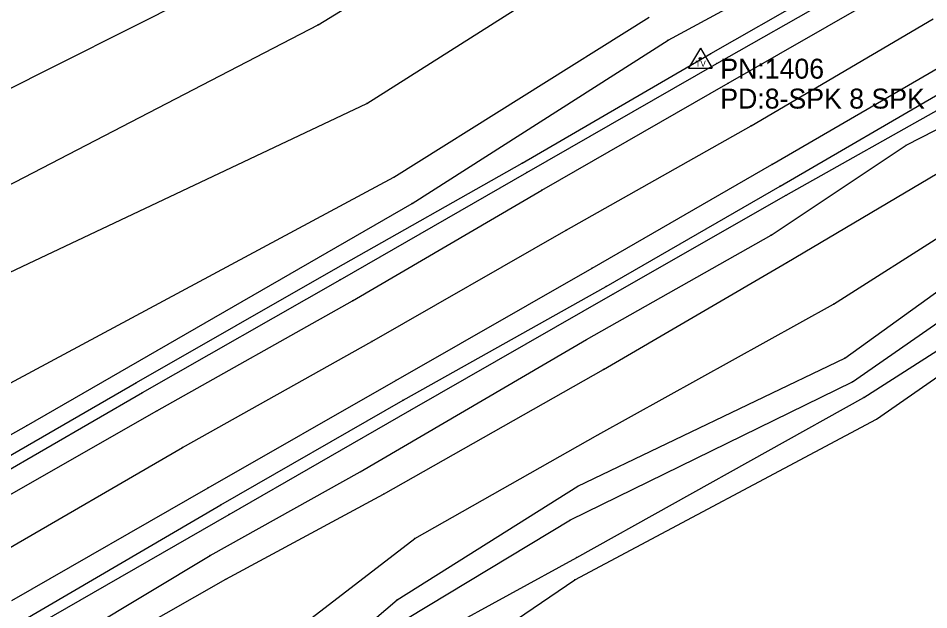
# Model space of a CAD drawing. Extents: x 1419505 to 1434054, y 1956910 to 1968644.
# Drawn here: x 1420365.7 to 1420594.1, y 1957394.5 to 1957542.8 of the extents above; entities that cross this region are included whole.
import ezdxf

# ---------------------------------------------------------------- set-up
doc = ezdxf.new("R2010")
doc.units = 0
for name, color, linetype in [('S_BREAKLINE', 7, 'Continuous'), ('S_DITCHLINE', 7, 'Continuous'), ('S_EDGE_PAVEMENT', 7, 'Continuous'), ('S_GRD_PT_SYM', 7, 'Continuous'), ('S_PAVEMENT_CROWN', 7, 'Continuous'), ('S_RDW_PT_SYM', 7, 'Continuous'), ('S_SECONDARY_CTL', 7, 'Continuous'), ('S_SECONDARY_CTL_ANNOT', 7, 'Continuous'), ('S_SHOULDER', 7, 'Continuous')]:
    doc.layers.add(name, color=color, linetype=linetype)

msp = doc.modelspace()

# ---------------------------------------------------------------- linework, layer by layer
at = {"layer": 'S_BREAKLINE'}
for p, q in [((1420440.9487, 1957541.147), (1420500.0875, 1957577.4944)), ((1420528.7223, 1957537.3228), (1420582.9688, 1957566.8997)), ((1420336.8469, 1957511.6521), (1420430.621, 1957558.8422)), ((1420453.1484, 1957521.3868), (1420512.2663, 1957558.9042)), ((1420539.463, 1957533.9656), (1420585.467, 1957560.2123)), ((1420459.9679, 1957502.9656), (1420523.993, 1957543.0132)), ((1420335.9639, 1957486.7575), (1420440.9487, 1957541.147)), ((1420464.5292, 1957496.3902), (1420528.7223, 1957537.3228)), ((1420588.4272, 1957510.9861), (1420638.2634, 1957536.4857)), ((1420492.082, 1957506.4418), (1420539.463, 1957533.9656)), ((1420558.3322, 1957498.4813), (1420604.7072, 1957524.557)), ((1420342.7853, 1957469.2664), (1420453.1484, 1957521.3868)), ((1420554.566, 1957488.4236), (1420588.4272, 1957510.9861)), ((1420445.4049, 1957480.0481), (1420492.082, 1957506.4418)), ((1420558.5302, 1957481.5912), (1420598.4178, 1957505.2107)), ((1420361.3455, 1957450.0972), (1420459.9679, 1957502.9656)), ((1420367.7909, 1957440.5896), (1420464.5292, 1957496.3902)), ((1420514.8634, 1957473.6247), (1420558.3322, 1957498.4813)), ((1420570.161, 1957471.0985), (1420610.1676, 1957496.5682)), ((1420573.0112, 1957457.6237), (1420619.5492, 1957491.0488)), ((1420508.274, 1957462.254), (1420554.566, 1957488.4236)), ((1420512.5023, 1957454.7755), (1420558.5302, 1957481.5912)), ((1420581.0057, 1957442.2667), (1420636.4663, 1957481.1622)), ((1420395.4067, 1957451.5023), (1420445.4049, 1957480.0481)), ((1420463.9601, 1957444.4428), (1420514.8634, 1957473.6247)), ((1420511.1042, 1957438.3474), (1420570.161, 1957471.0985)), ((1420451.5093, 1957429.0728), (1420508.274, 1957462.254)), ((1420506.0919, 1957425.5396), (1420573.0112, 1957457.6237)), ((1420457.3207, 1957423.4785), (1420512.5023, 1957454.7755)), ((1420349.1857, 1957424.8305), (1420395.4067, 1957451.5023)), ((1420418.6102, 1957418.4271), (1420463.9601, 1957444.4428)), ((1420505.3308, 1957402.0491), (1420581.0057, 1957442.2667)), ((1420246.7721, 1957373.2022), (1420367.7909, 1957440.5896)), ((1420465.1742, 1957412.4227), (1420511.1042, 1957438.3474)), ((1420413.8669, 1957408.1525), (1420451.5093, 1957429.0728)), ((1420417.8422, 1957402.2331), (1420457.3207, 1957423.4785)), ((1420460.7409, 1957397.0417), (1420506.0919, 1957425.5396)), ((1420367.2719, 1957388.9172), (1420418.6102, 1957418.4271)), ((1420427.1558, 1957383.1318), (1420465.1742, 1957412.4227)), ((1420378.5366, 1957386.9371), (1420413.8669, 1957408.1525)), ((1420382.7719, 1957382.3268), (1420417.8422, 1957402.2331)), ((1420451.2933, 1957365.4267), (1420505.3308, 1957402.0491)), ((1420433.9602, 1957374.1033), (1420460.7409, 1957397.0417))]:
    msp.add_line(p, q, dxfattribs=at)
at = {"layer": 'S_DITCHLINE'}
for p, q in [((1420574.9243, 1957451.6853), (1420624.6025, 1957486.1255)), ((1420577.8055, 1957447.707), (1420634.0221, 1957483.6623)), ((1420504.2557, 1957417.073), (1420574.9243, 1957451.6853)), ((1420505.7998, 1957407.6324), (1420577.8055, 1957447.707)), ((1420454.7835, 1957387.2761), (1420504.2557, 1957417.073)), ((1420449.0972, 1957376.6484), (1420505.7998, 1957407.6324))]:
    msp.add_line(p, q, dxfattribs=at)
at = {"layer": 'S_EDGE_PAVEMENT'}
for p, q in [((1420543.8053, 1957526.5091), (1420589.4702, 1957552.7048)), ((1420554.712, 1957506.0958), (1420600.3439, 1957532.6105)), ((1420497.0183, 1957499.6924), (1420543.8053, 1957526.5091)), ((1420509.6311, 1957480.1821), (1420554.712, 1957506.0958)), ((1420449.5322, 1957471.9216), (1420497.0183, 1957499.6924)), ((1420460.4209, 1957451.9523), (1420509.6311, 1957480.1821)), ((1420400.517, 1957444.3878), (1420449.5322, 1957471.9216)), ((1420413.3409, 1957425.0856), (1420460.4209, 1957451.9523)), ((1420352.896, 1957417.206), (1420400.517, 1957444.3878)), ((1420364.1637, 1957396.8567), (1420413.3409, 1957425.0856))]:
    msp.add_line(p, q, dxfattribs=at)
at = {"layer": 'S_GRD_PT_SYM'}
for points in [[(1420440.9487, 1957541.147), (1420440.9487, 1957541.197), (1420440.9487, 1957541.147), (1420440.8987, 1957541.147), (1420440.9487, 1957541.147), (1420440.9487, 1957541.097), (1420440.9487, 1957541.147), (1420440.9987, 1957541.147)], [(1420528.7223, 1957537.3228), (1420528.7223, 1957537.3728), (1420528.7223, 1957537.3228), (1420528.6723, 1957537.3228), (1420528.7223, 1957537.3228), (1420528.7223, 1957537.2728), (1420528.7223, 1957537.3228), (1420528.7723, 1957537.3228)], [(1420539.463, 1957533.9656), (1420539.463, 1957534.0156), (1420539.463, 1957533.9656), (1420539.413, 1957533.9656), (1420539.463, 1957533.9656), (1420539.463, 1957533.9156), (1420539.463, 1957533.9656), (1420539.513, 1957533.9656)], [(1420453.1484, 1957521.3868), (1420453.1484, 1957521.4368), (1420453.1484, 1957521.3868), (1420453.0984, 1957521.3868), (1420453.1484, 1957521.3868), (1420453.1484, 1957521.3368), (1420453.1484, 1957521.3868), (1420453.1984, 1957521.3868)], [(1420588.4272, 1957510.9861), (1420588.4272, 1957511.0361), (1420588.4272, 1957510.9861), (1420588.3772, 1957510.9861), (1420588.4272, 1957510.9861), (1420588.4272, 1957510.9361), (1420588.4272, 1957510.9861), (1420588.4772, 1957510.9861)], [(1420492.082, 1957506.4418), (1420492.082, 1957506.4918), (1420492.082, 1957506.4418), (1420492.032, 1957506.4418), (1420492.082, 1957506.4418), (1420492.082, 1957506.3918), (1420492.082, 1957506.4418), (1420492.132, 1957506.4418)], [(1420459.9679, 1957502.9656), (1420459.9679, 1957503.0156), (1420459.9679, 1957502.9656), (1420459.9179, 1957502.9656), (1420459.9679, 1957502.9656), (1420459.9679, 1957502.9156), (1420459.9679, 1957502.9656), (1420460.0179, 1957502.9656)], [(1420464.5292, 1957496.3902), (1420464.5292, 1957496.4402), (1420464.5292, 1957496.3902), (1420464.4792, 1957496.3902), (1420464.5292, 1957496.3902), (1420464.5292, 1957496.3402), (1420464.5292, 1957496.3902), (1420464.5792, 1957496.3902)], [(1420558.3322, 1957498.4813), (1420558.3322, 1957498.5313), (1420558.3322, 1957498.4813), (1420558.2822, 1957498.4813), (1420558.3322, 1957498.4813), (1420558.3322, 1957498.4313), (1420558.3322, 1957498.4813), (1420558.3822, 1957498.4813)], [(1420554.566, 1957488.4236), (1420554.566, 1957488.4736), (1420554.566, 1957488.4236), (1420554.516, 1957488.4236), (1420554.566, 1957488.4236), (1420554.566, 1957488.3736), (1420554.566, 1957488.4236), (1420554.616, 1957488.4236)], [(1420558.5302, 1957481.5912), (1420558.5302, 1957481.6412), (1420558.5302, 1957481.5912), (1420558.4802, 1957481.5912), (1420558.5302, 1957481.5912), (1420558.5302, 1957481.5412), (1420558.5302, 1957481.5912), (1420558.5802, 1957481.5912)], [(1420445.4049, 1957480.0481), (1420445.4049, 1957480.0981), (1420445.4049, 1957480.0481), (1420445.3549, 1957480.0481), (1420445.4049, 1957480.0481), (1420445.4049, 1957479.9981), (1420445.4049, 1957480.0481), (1420445.4549, 1957480.0481)], [(1420514.8634, 1957473.6247), (1420514.8634, 1957473.6747), (1420514.8634, 1957473.6247), (1420514.8134, 1957473.6247), (1420514.8634, 1957473.6247), (1420514.8634, 1957473.5747), (1420514.8634, 1957473.6247), (1420514.9134, 1957473.6247)], [(1420570.161, 1957471.0985), (1420570.161, 1957471.1485), (1420570.161, 1957471.0985), (1420570.111, 1957471.0985), (1420570.161, 1957471.0985), (1420570.161, 1957471.0485), (1420570.161, 1957471.0985), (1420570.211, 1957471.0985)], [(1420508.274, 1957462.254), (1420508.274, 1957462.304), (1420508.274, 1957462.254), (1420508.224, 1957462.254), (1420508.274, 1957462.254), (1420508.274, 1957462.204), (1420508.274, 1957462.254), (1420508.324, 1957462.254)], [(1420573.0112, 1957457.6237), (1420573.0112, 1957457.6737), (1420573.0112, 1957457.6237), (1420572.9612, 1957457.6237), (1420573.0112, 1957457.6237), (1420573.0112, 1957457.5737), (1420573.0112, 1957457.6237), (1420573.0612, 1957457.6237)], [(1420512.5023, 1957454.7755), (1420512.5023, 1957454.8255), (1420512.5023, 1957454.7755), (1420512.4523, 1957454.7755), (1420512.5023, 1957454.7755), (1420512.5023, 1957454.7255), (1420512.5023, 1957454.7755), (1420512.5523, 1957454.7755)], [(1420395.4067, 1957451.5023), (1420395.4067, 1957451.5523), (1420395.4067, 1957451.5023), (1420395.3567, 1957451.5023), (1420395.4067, 1957451.5023), (1420395.4067, 1957451.4523), (1420395.4067, 1957451.5023), (1420395.4567, 1957451.5023)], [(1420574.9243, 1957451.6853), (1420574.9243, 1957451.7353), (1420574.9243, 1957451.6853), (1420574.8743, 1957451.6853), (1420574.9243, 1957451.6853), (1420574.9243, 1957451.6353), (1420574.9243, 1957451.6853), (1420574.9743, 1957451.6853)], [(1420577.8055, 1957447.707), (1420577.8055, 1957447.757), (1420577.8055, 1957447.707), (1420577.7555, 1957447.707), (1420577.8055, 1957447.707), (1420577.8055, 1957447.657), (1420577.8055, 1957447.707), (1420577.8555, 1957447.707)], [(1420463.9601, 1957444.4428), (1420463.9601, 1957444.4928), (1420463.9601, 1957444.4428), (1420463.9101, 1957444.4428), (1420463.9601, 1957444.4428), (1420463.9601, 1957444.3928), (1420463.9601, 1957444.4428), (1420464.0101, 1957444.4428)], [(1420581.0057, 1957442.2667), (1420581.0057, 1957442.3167), (1420581.0057, 1957442.2667), (1420580.9557, 1957442.2667), (1420581.0057, 1957442.2667), (1420581.0057, 1957442.2167), (1420581.0057, 1957442.2667), (1420581.0557, 1957442.2667)], [(1420367.7909, 1957440.5896), (1420367.7909, 1957440.6396), (1420367.7909, 1957440.5896), (1420367.7409, 1957440.5896), (1420367.7909, 1957440.5896), (1420367.7909, 1957440.5396), (1420367.7909, 1957440.5896), (1420367.8409, 1957440.5896)], [(1420511.1042, 1957438.3474), (1420511.1042, 1957438.3974), (1420511.1042, 1957438.3474), (1420511.0542, 1957438.3474), (1420511.1042, 1957438.3474), (1420511.1042, 1957438.2974), (1420511.1042, 1957438.3474), (1420511.1542, 1957438.3474)], [(1420451.5093, 1957429.0728), (1420451.5093, 1957429.1228), (1420451.5093, 1957429.0728), (1420451.4593, 1957429.0728), (1420451.5093, 1957429.0728), (1420451.5093, 1957429.0228), (1420451.5093, 1957429.0728), (1420451.5593, 1957429.0728)], [(1420506.0919, 1957425.5396), (1420506.0919, 1957425.5896), (1420506.0919, 1957425.5396), (1420506.0419, 1957425.5396), (1420506.0919, 1957425.5396), (1420506.0919, 1957425.4896), (1420506.0919, 1957425.5396), (1420506.1419, 1957425.5396)], [(1420457.3207, 1957423.4785), (1420457.3207, 1957423.5285), (1420457.3207, 1957423.4785), (1420457.2707, 1957423.4785), (1420457.3207, 1957423.4785), (1420457.3207, 1957423.4285), (1420457.3207, 1957423.4785), (1420457.3707, 1957423.4785)], [(1420418.6102, 1957418.4271), (1420418.6102, 1957418.4771), (1420418.6102, 1957418.4271), (1420418.5602, 1957418.4271), (1420418.6102, 1957418.4271), (1420418.6102, 1957418.3771), (1420418.6102, 1957418.4271), (1420418.6602, 1957418.4271)], [(1420504.2557, 1957417.073), (1420504.2557, 1957417.123), (1420504.2557, 1957417.073), (1420504.2057, 1957417.073), (1420504.2557, 1957417.073), (1420504.2557, 1957417.023), (1420504.2557, 1957417.073), (1420504.3057, 1957417.073)], [(1420465.1742, 1957412.4227), (1420465.1742, 1957412.4727), (1420465.1742, 1957412.4227), (1420465.1242, 1957412.4227), (1420465.1742, 1957412.4227), (1420465.1742, 1957412.3727), (1420465.1742, 1957412.4227), (1420465.2242, 1957412.4227)], [(1420413.8669, 1957408.1525), (1420413.8669, 1957408.2025), (1420413.8669, 1957408.1525), (1420413.8169, 1957408.1525), (1420413.8669, 1957408.1525), (1420413.8669, 1957408.1025), (1420413.8669, 1957408.1525), (1420413.9169, 1957408.1525)], [(1420505.7998, 1957407.6324), (1420505.7998, 1957407.6824), (1420505.7998, 1957407.6324), (1420505.7498, 1957407.6324), (1420505.7998, 1957407.6324), (1420505.7998, 1957407.5824), (1420505.7998, 1957407.6324), (1420505.8498, 1957407.6324)], [(1420417.8422, 1957402.2331), (1420417.8422, 1957402.2831), (1420417.8422, 1957402.2331), (1420417.7922, 1957402.2331), (1420417.8422, 1957402.2331), (1420417.8422, 1957402.1831), (1420417.8422, 1957402.2331), (1420417.8922, 1957402.2331)], [(1420505.3308, 1957402.0491), (1420505.3308, 1957402.0991), (1420505.3308, 1957402.0491), (1420505.2808, 1957402.0491), (1420505.3308, 1957402.0491), (1420505.3308, 1957401.9991), (1420505.3308, 1957402.0491), (1420505.3808, 1957402.0491)], [(1420460.7409, 1957397.0417), (1420460.7409, 1957397.0917), (1420460.7409, 1957397.0417), (1420460.6909, 1957397.0417), (1420460.7409, 1957397.0417), (1420460.7409, 1957396.9917), (1420460.7409, 1957397.0417), (1420460.7909, 1957397.0417)]]:
    msp.add_lwpolyline(points, dxfattribs=at)
at = {"layer": 'S_PAVEMENT_CROWN'}
for p, q in [((1420549.5467, 1957515.8474), (1420595.2166, 1957542.6141)), ((1420503.1527, 1957489.6457), (1420549.5467, 1957515.8474)), ((1420454.4075, 1957461.7469), (1420503.1527, 1957489.6457)), ((1420406.9165, 1957435.2332), (1420454.4075, 1957461.7469)), ((1420358.3463, 1957407.0474), (1420406.9165, 1957435.2332))]:
    msp.add_line(p, q, dxfattribs=at)
at = {"layer": 'S_RDW_PT_SYM'}
for points in [[(1420540.9201, 1957531.4744), (1420540.9201, 1957531.5244), (1420540.9201, 1957531.4744), (1420540.8701, 1957531.4744), (1420540.9201, 1957531.4744), (1420540.9201, 1957531.4244), (1420540.9201, 1957531.4744), (1420540.9701, 1957531.4744)], [(1420543.8053, 1957526.5091), (1420543.8053, 1957526.5591), (1420543.8053, 1957526.5091), (1420543.7553, 1957526.5091), (1420543.8053, 1957526.5091), (1420543.8053, 1957526.4591), (1420543.8053, 1957526.5091), (1420543.8553, 1957526.5091)], [(1420549.5467, 1957515.8474), (1420549.5467, 1957515.8974), (1420549.5467, 1957515.8474), (1420549.4967, 1957515.8474), (1420549.5467, 1957515.8474), (1420549.5467, 1957515.7974), (1420549.5467, 1957515.8474), (1420549.5967, 1957515.8474)], [(1420554.712, 1957506.0958), (1420554.712, 1957506.1458), (1420554.712, 1957506.0958), (1420554.662, 1957506.0958), (1420554.712, 1957506.0958), (1420554.712, 1957506.0458), (1420554.712, 1957506.0958), (1420554.762, 1957506.0958)], [(1420493.276, 1957504.1447), (1420493.276, 1957504.1947), (1420493.276, 1957504.1447), (1420493.226, 1957504.1447), (1420493.276, 1957504.1447), (1420493.276, 1957504.0947), (1420493.276, 1957504.1447), (1420493.326, 1957504.1447)], [(1420497.0183, 1957499.6924), (1420497.0183, 1957499.7424), (1420497.0183, 1957499.6924), (1420496.9683, 1957499.6924), (1420497.0183, 1957499.6924), (1420497.0183, 1957499.6424), (1420497.0183, 1957499.6924), (1420497.0683, 1957499.6924)], [(1420556.7851, 1957500.7344), (1420556.7851, 1957500.7844), (1420556.7851, 1957500.7344), (1420556.7351, 1957500.7344), (1420556.7851, 1957500.7344), (1420556.7851, 1957500.6844), (1420556.7851, 1957500.7344), (1420556.8351, 1957500.7344)], [(1420503.1527, 1957489.6457), (1420503.1527, 1957489.6957), (1420503.1527, 1957489.6457), (1420503.1027, 1957489.6457), (1420503.1527, 1957489.6457), (1420503.1527, 1957489.5957), (1420503.1527, 1957489.6457), (1420503.2027, 1957489.6457)], [(1420509.6311, 1957480.1821), (1420509.6311, 1957480.2321), (1420509.6311, 1957480.1821), (1420509.5811, 1957480.1821), (1420509.6311, 1957480.1821), (1420509.6311, 1957480.1321), (1420509.6311, 1957480.1821), (1420509.6811, 1957480.1821)], [(1420446.461, 1957477.2169), (1420446.461, 1957477.2669), (1420446.461, 1957477.2169), (1420446.411, 1957477.2169), (1420446.461, 1957477.2169), (1420446.461, 1957477.1669), (1420446.461, 1957477.2169), (1420446.511, 1957477.2169)], [(1420513.1603, 1957475.5458), (1420513.1603, 1957475.5958), (1420513.1603, 1957475.5458), (1420513.1103, 1957475.5458), (1420513.1603, 1957475.5458), (1420513.1603, 1957475.4958), (1420513.1603, 1957475.5458), (1420513.2103, 1957475.5458)], [(1420449.5322, 1957471.9216), (1420449.5322, 1957471.9716), (1420449.5322, 1957471.9216), (1420449.4822, 1957471.9216), (1420449.5322, 1957471.9216), (1420449.5322, 1957471.8716), (1420449.5322, 1957471.9216), (1420449.5822, 1957471.9216)], [(1420454.4075, 1957461.7469), (1420454.4075, 1957461.7969), (1420454.4075, 1957461.7469), (1420454.3575, 1957461.7469), (1420454.4075, 1957461.7469), (1420454.4075, 1957461.6969), (1420454.4075, 1957461.7469), (1420454.4575, 1957461.7469)], [(1420460.4209, 1957451.9523), (1420460.4209, 1957452.0023), (1420460.4209, 1957451.9523), (1420460.3709, 1957451.9523), (1420460.4209, 1957451.9523), (1420460.4209, 1957451.9023), (1420460.4209, 1957451.9523), (1420460.4709, 1957451.9523)], [(1420396.9288, 1957448.9981), (1420396.9288, 1957449.0481), (1420396.9288, 1957448.9981), (1420396.8788, 1957448.9981), (1420396.9288, 1957448.9981), (1420396.9288, 1957448.9481), (1420396.9288, 1957448.9981), (1420396.9788, 1957448.9981)], [(1420462.265, 1957447.075), (1420462.265, 1957447.125), (1420462.265, 1957447.075), (1420462.215, 1957447.075), (1420462.265, 1957447.075), (1420462.265, 1957447.025), (1420462.265, 1957447.075), (1420462.315, 1957447.075)], [(1420400.517, 1957444.3878), (1420400.517, 1957444.4378), (1420400.517, 1957444.3878), (1420400.467, 1957444.3878), (1420400.517, 1957444.3878), (1420400.517, 1957444.3378), (1420400.517, 1957444.3878), (1420400.567, 1957444.3878)], [(1420406.9165, 1957435.2332), (1420406.9165, 1957435.2832), (1420406.9165, 1957435.2332), (1420406.8665, 1957435.2332), (1420406.9165, 1957435.2332), (1420406.9165, 1957435.1832), (1420406.9165, 1957435.2332), (1420406.9665, 1957435.2332)], [(1420413.3409, 1957425.0856), (1420413.3409, 1957425.1356), (1420413.3409, 1957425.0856), (1420413.2909, 1957425.0856), (1420413.3409, 1957425.0856), (1420413.3409, 1957425.0356), (1420413.3409, 1957425.0856), (1420413.3909, 1957425.0856)], [(1420416.5501, 1957420.7973), (1420416.5501, 1957420.8473), (1420416.5501, 1957420.7973), (1420416.5001, 1957420.7973), (1420416.5501, 1957420.7973), (1420416.5501, 1957420.7473), (1420416.5501, 1957420.7973), (1420416.6001, 1957420.7973)]]:
    msp.add_lwpolyline(points, dxfattribs=at)
at = {"layer": 'S_SECONDARY_CTL'}
for p, q in [((1420536.8068, 1957535.2496), (1420533.7968, 1957530.2957)), ((1420536.8068, 1957535.2496), (1420539.7541, 1957530.2957)), ((1420533.7968, 1957530.2957), (1420539.7541, 1957530.2957))]:
    msp.add_line(p, q, dxfattribs=at)
for radius in [0.3111, 0.1827, 0.1033]:
    msp.add_circle((1420536.8068, 1957532.6395), radius, dxfattribs=at)
at = {"layer": 'S_SHOULDER'}
for p, q in [((1420540.9201, 1957531.4744), (1420587.3941, 1957557.7871)), ((1420493.276, 1957504.1447), (1420540.9201, 1957531.4744)), ((1420556.7851, 1957500.7344), (1420602.9521, 1957527.4942)), ((1420446.461, 1957477.2169), (1420493.276, 1957504.1447)), ((1420513.1603, 1957475.5458), (1420556.7851, 1957500.7344)), ((1420396.9288, 1957448.9981), (1420446.461, 1957477.2169)), ((1420462.265, 1957447.075), (1420513.1603, 1957475.5458)), ((1420350.7198, 1957422.2894), (1420396.9288, 1957448.9981)), ((1420416.5501, 1957420.7973), (1420462.265, 1957447.075)), ((1420366.0558, 1957391.3334), (1420416.5501, 1957420.7973))]:
    msp.add_line(p, q, dxfattribs=at)

# ---------------------------------------------------------------- texts
at = {"layer": 'S_SECONDARY_CTL'}
msp.add_text('TV', height=1.5, rotation=360, dxfattribs=at).set_placement((1420535.6021, 1957530.6282))
at = {"layer": 'S_SECONDARY_CTL_ANNOT'}
for s, p in [('PN:1406', (1420541.8068, 1957527.6395)), ('PD:8-SPK 8 SPK', (1420541.8068, 1957520.1395))]:
    msp.add_text(s, height=5, dxfattribs=at).set_placement(p)

doc.saveas('drawing.dxf')
